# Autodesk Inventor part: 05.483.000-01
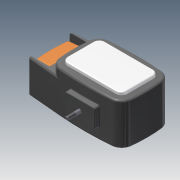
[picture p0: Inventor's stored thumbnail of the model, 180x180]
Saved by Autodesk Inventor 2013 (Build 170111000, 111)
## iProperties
Created: 2005-07
Part Number: 05.483.000-01
Material: Steel, Mild
Document SubType Name: Modeling
Designer: PVitaliy
Manufacturer: Standard
Standards Organization: Custom
Density: 7.86 g/cm^3
Author: PVitaliy
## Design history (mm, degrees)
derived "05.483.000.ipt"
body "Solid1"
tag "TaggingFeature2"
feature "Solid1::05.483.000.ipt" dims "d0" = 10
